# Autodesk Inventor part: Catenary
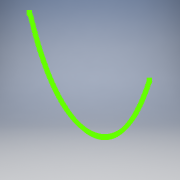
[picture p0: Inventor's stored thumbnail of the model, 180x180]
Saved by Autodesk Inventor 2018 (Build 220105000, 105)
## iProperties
Created: 2008-02
Part Number: Catenary
Document SubType Name: Modeling
Designer: Autodesk, Inc.
Density: 1 g/cm^3
Material: Generic
Appearance: Default
Author: Autodesk, Inc.
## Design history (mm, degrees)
sketch "Sketch1"
  geometry: 300 further points
  constraints: 300 other
